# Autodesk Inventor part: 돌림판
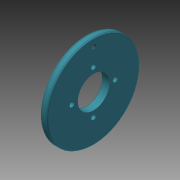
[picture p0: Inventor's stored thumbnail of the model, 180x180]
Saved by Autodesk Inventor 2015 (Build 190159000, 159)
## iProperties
Created: 2019-10
Part Number: 돌림판
Material: 스테인리스강
Document SubType Name: Modeling
Designer: mduedu
Density: 1 g/cm^3
Appearance: 커뎃 파란색
Author: mduedu
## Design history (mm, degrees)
sketch "스케치1" dims "d3" = 30
  geometry: C1 r 32 at (0, 0); C2 r 11 at (0, 0); C3 r 1.7 at (15, 0); C4 r 1.7 at (0, 15); C5 r 1.7 at (-15, 0); C6 r 1.7 at (0, -15); 2 further points
  constraints: 6 centre point, 3 coincident, 2 horizontal alignment, 11 other
  dimensions: "d0" = 64 diameter of C1; "d2" = 3.4 diameter of C3; "d4" = 22 diameter of C2; "d7" = 360 deg dimension on point (0, 0) C3.centre (derived)
extrude "돌출1" new body sketch "스케치1" distance "d9" = 5; taper "d10" = 0 deg
sketch "스케치2" dims "d11" = 54
  geometry: 3 further points
  constraints: 2 vertical alignment, 1 coincident, 2 other
hole "구멍1" sketch "스케치2" at (0, 27) diameter "d13" = 3.242; stored, may be unused: countersink angle "d17" = 90 deg, drill point angle "d19" = 118 deg; dims "d14" = 6, "d15" = 4, "d16" = 2, "d18" = 8
fillet "모깎기1" dims "d20" = 1
node "솔리드1"
